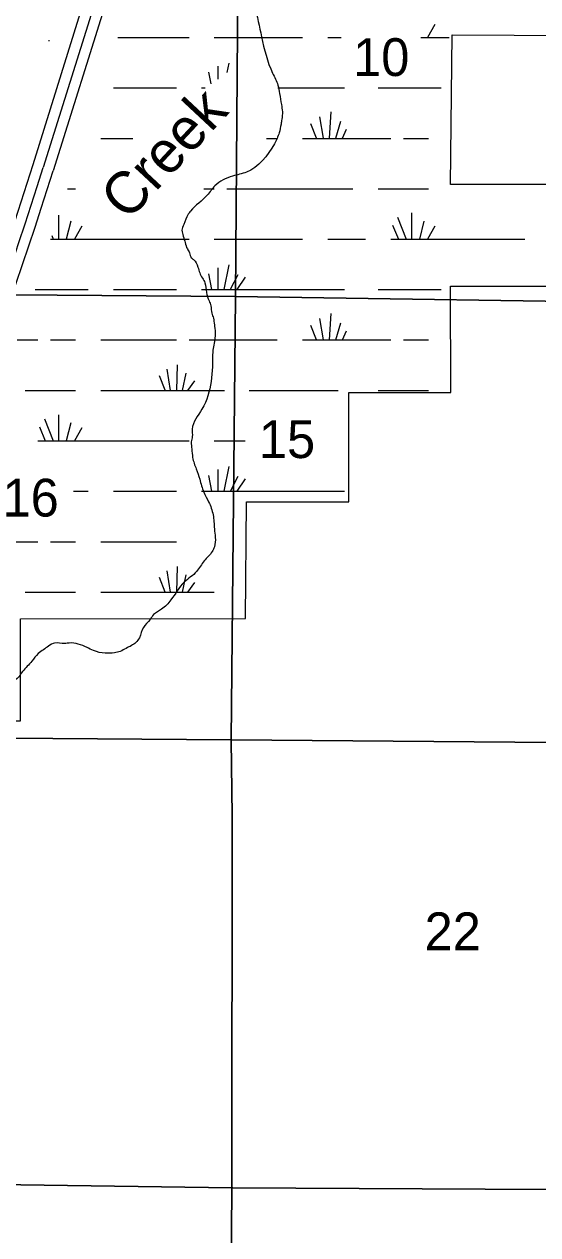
# Model space of a CAD drawing. Extents: x 380424 to 701066, y 1117407 to 1412949.
# Drawn here: x 524199 to 530309, y 1373482 to 1387886 of the extents above; entities that cross this region are included whole.
import ezdxf

# ---------------------------------------------------------------- set-up
doc = ezdxf.new("R2010")
doc.units = 0
for name, color, linetype in [('Cities Incorporated Area', 7, 'Continuous'), ('Interstate Divided Highway Outline and Fill', 7, 'Continuous'), ('Interstate Highway Center Lines', 7, 'Continuous'), ('Narrow River Creek and Branch and Slough', 7, 'Continuous'), ('Narrow River Creek and Branch and Slough Text', 7, 'Continuous'), ('Section Lines', 7, 'Continuous'), ('Section Numbers', 7, 'Continuous'), ('Swamps', 7, 'Continuous')]:
    doc.layers.add(name, color=color, linetype=linetype)

msp = doc.modelspace()

# ---------------------------------------------------------------- linework, layer by layer
at = {"layer": 'Cities Incorporated Area'}
msp.add_lwpolyline([(519001, 1373755), (521574, 1379045), (522696, 1379043), (523025, 1379596), (524154, 1379596), (524154, 1380812), (526832, 1380817), (526844, 1382202), (528060, 1382202), (528061, 1383504), (529275, 1383505), (529270, 1384771), (530889, 1384771), (530889, 1385981), (529270, 1385981), (529290, 1387758), (530767, 1387752), (529457, 1389968)], dxfattribs=at)
at = {"layer": 'Interstate Divided Highway Outline and Fill'}
for p, q in [((524305, 1386218), (525056, 1388622)), ((525295, 1388547), (524543, 1386143))]:
    msp.add_line(p, q, dxfattribs=at)
for radius in [49839, 50089]:
    msp.add_arc((476737, 1401092), radius, 334.0597, 342.6352, dxfattribs=at)
at = {"layer": 'Interstate Highway Center Lines'}
msp.add_line((525176, 1388584), (524424, 1386180), dxfattribs=at)
msp.add_arc((476737, 1401092), 49964, 334.0597, 342.6352, dxfattribs=at)
at = {"layer": 'Narrow River Creek and Branch and Slough'}
for points in [[(528670, 1391718), (528543, 1391624), (528455, 1391523), (528337, 1391377), (528199, 1391243), (528171, 1391183), (528163, 1391132), (528187, 1391030), (528250, 1390978), (528289, 1390868), (527931, 1391041), (527824, 1390998), (527785, 1390872), (527782, 1390816), (527793, 1390758), (527798, 1390705), (527787, 1390631), (527777, 1390594), (527750, 1390562), (527729, 1390536), (527687, 1390510), (527634, 1390473), (527529, 1390409), (527449, 1390298), (527338, 1390087), (527270, 1389892), (527254, 1389834), (527191, 1389670), (527148, 1389591), (527074, 1389464), (527016, 1389411), (526969, 1389369), (526879, 1389269), (526784, 1389184), (526766, 1389151), (526726, 1389052), (526699, 1388957), (526705, 1388915), (526710, 1388841), (526726, 1388741), (526747, 1388661), (526763, 1388619), (526784, 1388577), (526842, 1388429), (526942, 1388102), (527022, 1387737), (527154, 1387304), (527217, 1387162), (527238, 1387061), (527259, 1386929), (527270, 1386845), (527264, 1386755), (527254, 1386697), (527232, 1386594), (527175, 1386464), (526842, 1386126), (526678, 1386079), (526467, 1385963), (526377, 1385852), (526177, 1385662), (526151, 1385625), (526097, 1385503), (526076, 1385435), (526092, 1385366), (526113, 1385287), (526140, 1385213), (526166, 1385165), (526187, 1385107), (526214, 1385086), (526266, 1384996), (526287, 1384928), (526319, 1384864), (526348, 1384810), (526367, 1384695), (526398, 1384595), (526419, 1384537), (526430, 1384447), (526451, 1384389), (526456, 1384352), (526467, 1384268), (526467, 1384151), (526441, 1383988)], [(526441, 1383988), (526314, 1383306), (526198, 1383069), (526198, 1382979), (526187, 1382916), (526192, 1382831), (526203, 1382731), (526245, 1382594), (526287, 1382472), (526335, 1382319), (526393, 1382203), (526446, 1382050), (526462, 1381881), (526472, 1381780), (526462, 1381669), (526435, 1381611), (526340, 1381500), (526250, 1381374), (526103, 1381247), (525944, 1381036), (525833, 1380925), (525738, 1380861), (525696, 1380803), (525617, 1380708), (525569, 1380587), (525527, 1380529), (525474, 1380492), (525411, 1380460), (525342, 1380423), (525273, 1380407), (525163, 1380402), (525025, 1380434), (524946, 1380471), (524735, 1380523), (524682, 1380518), (524561, 1380523), (524487, 1380486), (524429, 1380444), (524365, 1380397), (524291, 1380307), (524180, 1380185), (524117, 1380101), (524027, 1380038), (523974, 1380006), (523863, 1379990), (523758, 1379985), (523599, 1379990), (523356, 1379985), (523256, 1379964), (523077, 1379916), (523024, 1379874), (522992, 1379847), (522976, 1379826), (522955, 1379789), (522945, 1379758), (522939, 1379705), (522966, 1379641), (522987, 1379589), (523034, 1379515), (523087, 1379372), (523103, 1379314), (523108, 1379293), (523108, 1379245), (523108, 1379214), (523108, 1379171), (523098, 1379124), (523087, 1379066), (523066, 1379018), (523061, 1378976), (523045, 1378897), (523034, 1378855), (523040, 1378807), (523061, 1378786), (523124, 1378723), (523209, 1378664), (523240, 1378622), (523282, 1378575), (523309, 1378490), (523341, 1378400), (523330, 1378342), (523319, 1378268), (523288, 1378210), (523267, 1378158), (523209, 1378084), (523161, 1378004), (523129, 1377957), (523129, 1377930), (523103, 1377814), (523108, 1377714), (523103, 1377656), (523119, 1377577), (523119, 1377550), (523204, 1377419)]]:
    msp.add_spline(points, degree=3, dxfattribs=at)
at = {"layer": 'Section Lines'}
for points in [[(526752, 1389920), (526712, 1384648), (526707, 1384648), (521413, 1384687), (521471, 1389984)], [(532015, 1389860), (532015, 1389850), (531984, 1384568), (531976, 1384568), (526712, 1384648), (526752, 1389920), (526759, 1389920)], [(526712, 1384648), (526712, 1384642), (526663, 1379370), (521351, 1379411), (521413, 1384687), (526707, 1384648)], [(531984, 1384568), (531964, 1379326), (526663, 1379370), (526712, 1384642), (526712, 1384648), (531976, 1384568)], [(526663, 1379370), (526663, 1379363), (526672, 1378473), (526670, 1374041), (521365, 1374116), (521382, 1378488), (521351, 1379405), (521351, 1379411)], [(531964, 1379326), (531959, 1378434), (531935, 1374014), (526679, 1374041), (526670, 1374041), (526672, 1378473), (526663, 1379363), (526663, 1379370)], [(526670, 1374041), (526628, 1368762), (526620, 1368762), (521346, 1368815), (521334, 1368815), (521365, 1374116)], [(531935, 1374014), (531919, 1368754), (526628, 1368762), (526670, 1374041), (526679, 1374041)]]:
    msp.add_lwpolyline(points, close=True, dxfattribs=at)
at = {"layer": 'Swamps'}
for p, q in [((529086, 1387882), (528997, 1387729)), ((525710, 1387728), (526160, 1387728)), ((526460, 1387728), (527510, 1387728)), ((527810, 1387728), (527970, 1387728)), ((528919, 1387728), (529254, 1387728)), ((526634, 1387423), (526611, 1387311)), ((526392, 1387315), (526419, 1387177)), ((526501, 1387387), (526501, 1387234)), ((525260, 1387128), (525710, 1387128)), ((525710, 1387128), (526010, 1387128)), ((526310, 1387128), (526350, 1387128)), ((527216, 1387128), (528010, 1387128)), ((528410, 1387128), (529160, 1387128)), ((527831, 1386529), (527849, 1386845)), ((527675, 1386529), (527610, 1386701)), ((527760, 1386529), (527714, 1386783)), ((527908, 1386529), (527966, 1386733)), ((527985, 1386529), (528033, 1386637)), ((525110, 1386528), (525493, 1386528)), ((527081, 1386528), (527210, 1386528)), ((527510, 1386528), (528560, 1386528)), ((528710, 1386528), (529010, 1386528)), ((524712, 1385929), (524810, 1385929)), ((526334, 1385929), (526460, 1385929)), ((526610, 1385929), (528110, 1385929)), ((528410, 1385929), (529010, 1385929)), ((524608, 1385613), (524608, 1385329)), ((524753, 1385543), (524700, 1385328)), ((528639, 1385591), (528742, 1385329)), ((528808, 1385640), (528808, 1385329)), ((528953, 1385543), (528900, 1385328)), ((524886, 1385482), (524797, 1385329)), ((528579, 1385495), (528650, 1385329)), ((529086, 1385482), (528997, 1385329)), ((524511, 1385329), (525710, 1385329)), ((524526, 1385371), (524542, 1385329)), ((525710, 1385329), (526160, 1385329)), ((526460, 1385329), (527510, 1385329)), ((527810, 1385329), (528260, 1385329)), ((528560, 1385329), (529910, 1385329)), ((526501, 1384987), (526501, 1384729)), ((526634, 1385023), (526575, 1384729)), ((526392, 1384915), (526429, 1384729)), ((526742, 1384903), (526648, 1384728)), ((526827, 1384878), (526728, 1384729)), ((524328, 1384729), (524960, 1384729)), ((525260, 1384729), (525710, 1384729)), ((525710, 1384729), (526010, 1384729)), ((526310, 1384729), (528010, 1384729)), ((528410, 1384729), (529160, 1384729)), ((527831, 1384129), (527849, 1384445)), ((527675, 1384129), (527610, 1384301)), ((527760, 1384129), (527714, 1384383)), ((527908, 1384129), (527966, 1384333)), ((524510, 1384129), (524810, 1384129)), ((525110, 1384129), (525710, 1384129)), ((525710, 1384129), (526010, 1384129)), ((526160, 1384129), (527210, 1384129)), ((527510, 1384129), (528560, 1384129)), ((527985, 1384129), (528033, 1384237)), ((528710, 1384129), (529010, 1384129)), ((526016, 1383529), (526022, 1383832)), ((525875, 1383530), (525809, 1383702)), ((525938, 1383529), (525898, 1383782)), ((526083, 1383528), (526126, 1383734)), ((524210, 1383529), (524810, 1383529)), ((525110, 1383529), (525710, 1383529)), ((525710, 1383529), (526582, 1383529)), ((526145, 1383528), (526229, 1383642)), ((526877, 1383529), (527935, 1383529)), ((528410, 1383529), (529010, 1383529)), ((524608, 1383240), (524608, 1382929)), ((524379, 1383095), (524450, 1382929)), ((524439, 1383191), (524542, 1382929)), ((524753, 1383143), (524700, 1382928)), ((524886, 1383082), (524797, 1382929)), ((524360, 1382929), (525710, 1382929)), ((525710, 1382929), (526160, 1382929)), ((526460, 1382929), (526828, 1382929)), ((526501, 1382587), (526501, 1382329)), ((526634, 1382623), (526575, 1382329)), ((526392, 1382515), (526429, 1382329)), ((526742, 1382503), (526648, 1382328)), ((526827, 1382478), (526728, 1382329)), ((524785, 1382329), (524960, 1382329)), ((525260, 1382329), (525710, 1382329)), ((525710, 1382329), (526010, 1382329)), ((526310, 1382329), (528010, 1382329)), ((524510, 1381729), (524810, 1381729)), ((525110, 1381729), (525710, 1381729)), ((525710, 1381729), (526010, 1381729)), ((525938, 1381129), (525898, 1381382)), ((526016, 1381129), (526022, 1381432)), ((525875, 1381130), (525809, 1381302)), ((526083, 1381128), (526126, 1381334)), ((526145, 1381128), (526229, 1381242)), ((524210, 1381129), (524810, 1381129)), ((525110, 1381129), (525710, 1381129)), ((525710, 1381129), (526460, 1381129))]:
    msp.add_line(p, q, dxfattribs=at)
for points in [[(525313, 1387728), (525710, 1387728)], [(524488, 1387691), (524498, 1387691)], [(529910, 1385329), (530154, 1385329)], [(524117, 1384129), (524360, 1384129)], [(523804, 1381729), (524360, 1381729)]]:
    msp.add_lwpolyline(points, dxfattribs=at)

# ---------------------------------------------------------------- texts
at = {"layer": 'Narrow River Creek and Branch and Slough Text'}
msp.add_text('Creek', height=500, rotation=46.974, dxfattribs=at).set_placement((525430, 1385532))
at = {"layer": 'Section Numbers'}
for s, p in [('10', (528112, 1387270)), ('15', (526991, 1382724)), ('16', (523941, 1382028)), ('22', (528962, 1376868))]:
    msp.add_text(s, height=450, dxfattribs=at).set_placement(p)

doc.saveas('drawing.dxf')
